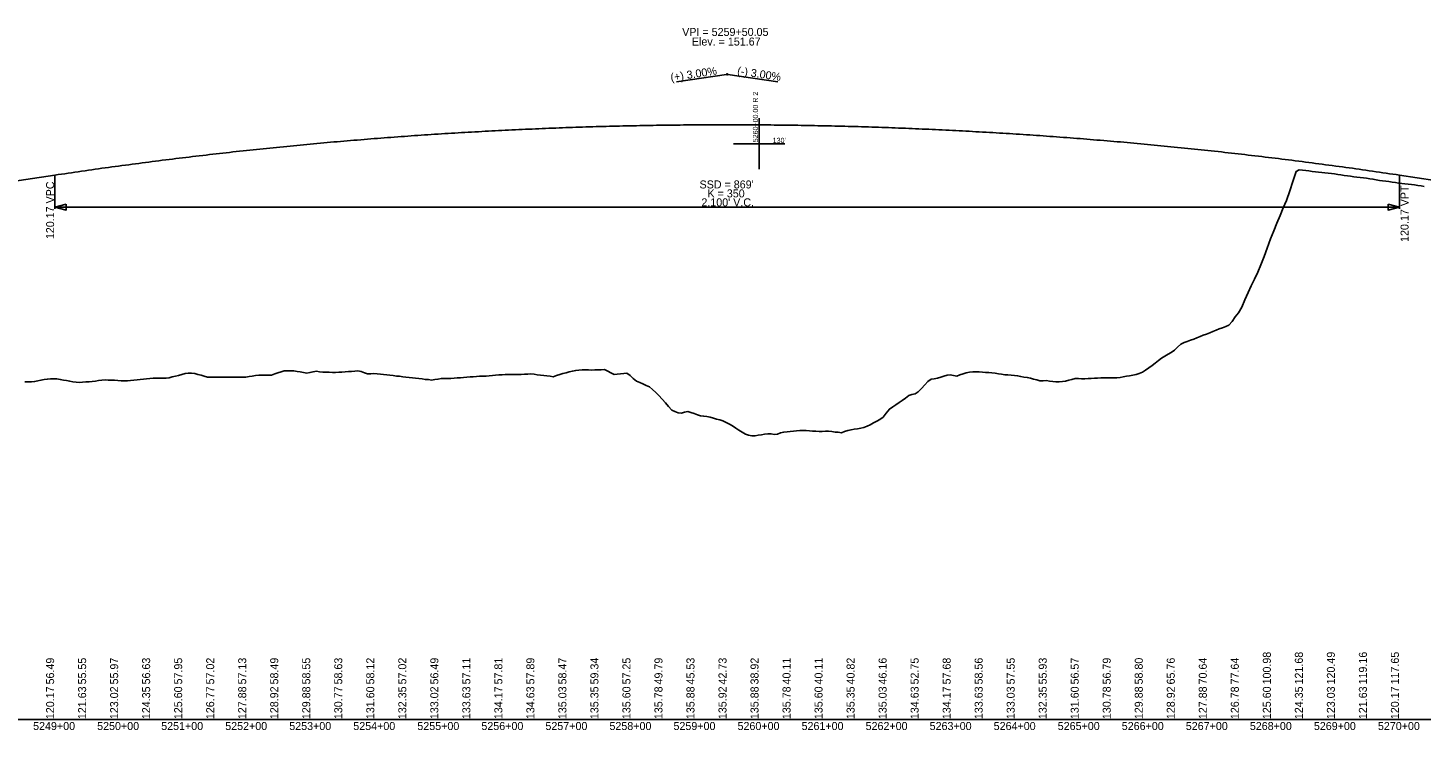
# Model space of a CAD drawing. Extents: x 2147288 to 2220488, y 740833 to 759333.
# Drawn here: x 2157239 to 2159415, y 758067 to 759164 of the extents above; entities that cross this region are included whole.
import ezdxf

# ---------------------------------------------------------------- set-up
doc = ezdxf.new("R2010")
doc.units = 0
for name, color, linetype in [('RD_DDB_GradeTX', 7, 'Continuous'), ('RD_DDB_Profile_EX', 7, 'Continuous'), ('RD_DDB_Profile_Lbl', 7, 'Continuous'), ('RD_DDB_Profile_PR', 7, 'Continuous'), ('RD_DDB_StaTX', 7, 'Continuous'), ('RD_DDB_StripGrade', 7, 'Continuous'), ('RD_DDB_VCLbl', 7, 'Continuous'), ('RD_GPK_Profile_Cell', 7, 'Continuous')]:
    doc.layers.add(name, color=color, linetype=linetype)

msp = doc.modelspace()

# ---------------------------------------------------------------- linework, layer by layer
at = {"layer": 'RD_DDB_GradeTX'}
for p, q in [((2158252, 759079.9), (2158330.1, 759091.6)), ((2158410.2, 759079.9), (2158332.1, 759091.6))]:
    msp.add_line(p, q, dxfattribs=at)
msp.add_circle((2158331.1, 759091.8), 1, dxfattribs=at)
at = {"layer": 'RD_DDB_Profile_EX'}
for points in [[(2159034.6, 758665.4), (2159039.6, 758669.9), (2159044.6, 758672.7), (2159049.6, 758674.2), (2159054.6, 758676.2), (2159059.6, 758678.2), (2159064.6, 758680.1), (2159069.6, 758682.1), (2159074.6, 758684.1), (2159079.6, 758686), (2159084.6, 758688), (2159089.6, 758690), (2159094.6, 758691.9), (2159099.6, 758693.9), (2159104.6, 758695.9), (2159109.6, 758697.8), (2159114.6, 758699.7), (2159119.6, 758705.5), (2159124.6, 758713), (2159129.6, 758718.9), (2159134.6, 758727.9), (2159139.6, 758739.3), (2159144.6, 758750.7), (2159149.6, 758761.4), (2159154.6, 758771.7), (2159159.6, 758782.7), (2159164.6, 758794.2), (2159169.6, 758806.9), (2159174.6, 758820.3), (2159179.6, 758834.5), (2159184.6, 758847.4), (2159189.6, 758859.5), (2159194.6, 758871.3), (2159199.6, 758883), (2159204.6, 758894.8), (2159209.6, 758909.7), (2159214.6, 758924.2), (2159219.6, 758940.1), (2159224.6, 758942.5), (2159229.6, 758942), (2159234.6, 758941.4), (2159239.6, 758940.9), (2159244.6, 758940.2), (2159249.6, 758939.6), (2159254.6, 758939.1), (2159259.6, 758938.5), (2159264.6, 758937.9), (2159269.6, 758937.3), (2159274.6, 758936.8), (2159279.6, 758936.1), (2159284.6, 758935.4), (2159289.6, 758934.7), (2159294.6, 758933.9), (2159299.6, 758933.3), (2159304.6, 758932.6), (2159309.6, 758931.9), (2159314.6, 758931.3), (2159319.6, 758930.7), (2159324.6, 758930.2), (2159329.6, 758929.5), (2159334.6, 758928.7), (2159339.6, 758928), (2159344.6, 758926.9), (2159349.6, 758926.1), (2159354.6, 758925.6), (2159359.6, 758924.9), (2159364.6, 758924.2), (2159369.6, 758923.4), (2159374.6, 758922.6), (2159379.6, 758921.9), (2159384.6, 758921.2), (2159389.6, 758920.6), (2159394.6, 758920.1), (2159399.6, 758919.5), (2159404.6, 758918.9), (2159409.6, 758918.2), (2159414.6, 758917.4), (2159419.6, 758916.6)], [(2158534.6, 758538.1), (2158539.6, 758538.9), (2158544.6, 758540.2), (2158549.6, 758542.2), (2158554.6, 758544.3), (2158559.6, 758547.1), (2158564.6, 758549.9), (2158569.6, 758552.7), (2158574.6, 758555.9), (2158579.6, 758562.3), (2158584.6, 758568.7), (2158589.6, 758572.3), (2158594.6, 758575.6), (2158599.6, 758578.9), (2158604.6, 758582.2), (2158609.6, 758586), (2158614.6, 758589.8), (2158619.6, 758591.7), (2158624.6, 758592.3), (2158629.6, 758595.5), (2158634.6, 758601), (2158639.6, 758606.4), (2158644.6, 758611.9), (2158649.6, 758615.4), (2158654.6, 758616.1), (2158659.6, 758617), (2158664.6, 758618.5), (2158669.6, 758620), (2158674.6, 758621.5), (2158679.6, 758622.2), (2158684.6, 758621), (2158689.6, 758620.4), (2158694.6, 758622.1), (2158699.6, 758623.8), (2158704.6, 758625.5), (2158709.6, 758626.6), (2158714.6, 758627), (2158719.6, 758627.1), (2158724.6, 758626.7), (2158729.6, 758626.3), (2158734.6, 758626), (2158739.6, 758625.7), (2158744.6, 758625.5), (2158749.6, 758624.8), (2158754.6, 758624), (2158759.6, 758623.2), (2158764.6, 758622.4), (2158769.6, 758622.1), (2158774.6, 758621.7), (2158779.6, 758621.4), (2158784.6, 758620.7), (2158789.6, 758619.5), (2158794.6, 758618.7), (2158799.6, 758618.1), (2158804.6, 758617), (2158809.6, 758615.6), (2158814.6, 758614.2), (2158819.6, 758612.8), (2158824.6, 758613), (2158829.6, 758613.3), (2158834.6, 758612.6), (2158839.6, 758612), (2158844.6, 758611.3), (2158849.6, 758611.1), (2158854.6, 758611.6), (2158859.6, 758612.5), (2158864.6, 758613.8), (2158869.6, 758615.1), (2158874.6, 758616.3), (2158879.6, 758616.3), (2158884.6, 758616.1), (2158889.6, 758616.2), (2158894.6, 758616.4), (2158899.6, 758616.6), (2158904.6, 758616.8), (2158909.6, 758617.2), (2158914.6, 758617.5), (2158919.6, 758617.4), (2158924.6, 758617.4), (2158929.6, 758617.4), (2158934.6, 758617.4), (2158939.6, 758617.4), (2158944.6, 758618.1), (2158949.6, 758619), (2158954.6, 758619.9), (2158959.6, 758620.8), (2158964.6, 758621.7), (2158969.6, 758622.6), (2158974.6, 758624.2), (2158979.6, 758626.5), (2158984.6, 758629.6), (2158989.6, 758633.1), (2158994.6, 758636.6), (2158999.6, 758640.5), (2159004.6, 758644.5), (2159009.6, 758648.4), (2159014.6, 758651.5), (2159019.6, 758654.4), (2159024.6, 758657.2), (2159029.6, 758660.9), (2159034.6, 758665.4)], [(2157234.6, 758611.4), (2157239.6, 758611.4), (2157244.6, 758611.3), (2157249.6, 758611.8), (2157254.6, 758612.8), (2157259.6, 758613.7), (2157264.6, 758614.7), (2157269.6, 758615.7), (2157274.6, 758615.9), (2157279.6, 758615.9), (2157284.6, 758615.8), (2157289.6, 758615.1), (2157294.6, 758614.1), (2157299.6, 758613.2), (2157304.6, 758612.2), (2157309.6, 758611.5), (2157314.6, 758611), (2157319.6, 758610.4), (2157324.6, 758610.6), (2157329.6, 758611.1), (2157334.6, 758611.5), (2157339.6, 758612), (2157344.6, 758612.6), (2157349.6, 758613.3), (2157354.6, 758614), (2157359.6, 758614.2), (2157364.6, 758614), (2157369.6, 758613.9), (2157374.6, 758613.7), (2157379.6, 758613.4), (2157384.6, 758613.1), (2157389.6, 758612.8), (2157394.6, 758613.1), (2157399.6, 758613.4), (2157404.6, 758613.7), (2157409.6, 758614.3), (2157414.6, 758614.9), (2157419.6, 758615.5), (2157424.6, 758616), (2157429.6, 758616.5), (2157434.6, 758616.9), (2157439.6, 758616.9), (2157444.6, 758616.9), (2157449.6, 758616.8), (2157454.6, 758616.8), (2157459.6, 758617.7), (2157464.6, 758618.9), (2157469.6, 758620.1), (2157474.6, 758621.4), (2157479.6, 758622.8), (2157484.6, 758624.1), (2157489.6, 758624.9), (2157494.6, 758624.6), (2157499.6, 758624.3), (2157504.6, 758622.9), (2157509.6, 758621.5), (2157514.6, 758620.2), (2157519.6, 758618.8), (2157524.6, 758618.6), (2157529.6, 758618.5), (2157534.6, 758618.5)], [(2157534.6, 758618.5), (2157539.6, 758618.6), (2157544.6, 758618.7), (2157549.6, 758618.7), (2157554.6, 758618.6), (2157559.6, 758618.5), (2157564.6, 758618.5), (2157569.6, 758618.4), (2157574.6, 758618.6), (2157579.6, 758618.8), (2157584.6, 758619.6), (2157589.6, 758620.4), (2157594.6, 758621), (2157599.6, 758621.5), (2157604.6, 758621.9), (2157609.6, 758621.9), (2157614.6, 758621.7), (2157619.6, 758621.8), (2157624.6, 758623.6), (2157629.6, 758625.3), (2157634.6, 758627.1), (2157639.6, 758628.6), (2157644.6, 758628.6), (2157649.6, 758628.5), (2157654.6, 758628.4), (2157659.6, 758627.6), (2157664.6, 758626.7), (2157669.6, 758625.8), (2157674.6, 758625), (2157679.6, 758625.8), (2157684.6, 758627), (2157689.6, 758627.8), (2157694.6, 758627.1), (2157699.6, 758626.4), (2157704.6, 758626.2), (2157709.6, 758626.2), (2157714.6, 758626.1), (2157719.6, 758626.1), (2157724.6, 758626.2), (2157729.6, 758626.5), (2157734.6, 758626.8), (2157739.6, 758627.2), (2157744.6, 758627.6), (2157749.6, 758628), (2157754.6, 758628.4), (2157759.6, 758627.3), (2157764.6, 758625.5), (2157769.6, 758623.9), (2157774.6, 758624), (2157779.6, 758624.1), (2157784.6, 758623.8), (2157789.6, 758623.3), (2157794.6, 758622.7), (2157799.6, 758622.2), (2157804.6, 758621.6), (2157809.6, 758621), (2157814.6, 758620.4), (2157819.6, 758619.9), (2157824.6, 758619.3), (2157829.6, 758618.7), (2157834.6, 758618.1), (2157839.6, 758617.5), (2157844.6, 758617), (2157849.6, 758616.4), (2157854.6, 758615.8), (2157859.6, 758615.2), (2157864.6, 758614.7), (2157869.6, 758614.1), (2157874.6, 758614.7), (2157879.6, 758615.6), (2157884.6, 758616.4), (2157889.6, 758616.4), (2157894.6, 758616.4), (2157899.6, 758616.6), (2157904.6, 758617), (2157909.6, 758617.3), (2157914.6, 758617.7), (2157919.6, 758618.1), (2157924.6, 758618.5), (2157929.6, 758618.9), (2157934.6, 758619.3), (2157939.6, 758619.7), (2157944.6, 758620), (2157949.6, 758620.1), (2157954.6, 758620.2), (2157959.6, 758620.6), (2157964.6, 758621.2), (2157969.6, 758621.8), (2157974.6, 758622.1), (2157979.6, 758622.4), (2157984.6, 758622.7), (2157989.6, 758623), (2157994.6, 758622.9), (2157999.6, 758622.7), (2158004.6, 758622.6), (2158009.6, 758622.9), (2158014.6, 758623.1), (2158019.6, 758623.4), (2158024.6, 758623.6), (2158029.6, 758623.1), (2158034.6, 758622.4)], [(2158034.6, 758622.4), (2158039.6, 758621.7), (2158044.6, 758621.1), (2158049.6, 758620.5), (2158054.6, 758619.9), (2158059.6, 758619.3), (2158064.6, 758621), (2158069.6, 758622.6), (2158074.6, 758624.1), (2158079.6, 758625.4), (2158084.6, 758626.7), (2158089.6, 758628), (2158094.6, 758629.2), (2158099.6, 758629.7), (2158104.6, 758630.2), (2158109.6, 758630.2), (2158114.6, 758629.9), (2158119.6, 758629.7), (2158124.6, 758629.9), (2158129.6, 758630.1), (2158134.6, 758630.3), (2158139.6, 758630.4), (2158144.6, 758628.2), (2158149.6, 758625.2), (2158154.6, 758623), (2158159.6, 758623.4), (2158164.6, 758623.9), (2158169.6, 758624.4), (2158174.6, 758624.9), (2158179.6, 758621.1), (2158184.6, 758616.5), (2158189.6, 758612.6), (2158194.6, 758610.3), (2158199.6, 758608), (2158204.6, 758605.8), (2158209.6, 758603.5), (2158214.6, 758599.1), (2158219.6, 758594.6), (2158224.6, 758589.7), (2158229.6, 758584.1), (2158234.6, 758578.4), (2158239.6, 758572.8), (2158244.6, 758567.2), (2158249.6, 758564.9), (2158254.6, 758562.7), (2158259.6, 758562.5), (2158264.6, 758563.9), (2158269.6, 758564.9), (2158274.6, 758563.2), (2158279.6, 758561.6), (2158284.6, 758559.9), (2158289.6, 758558.3), (2158294.6, 758557.4), (2158299.6, 758556.9), (2158304.6, 758556.1), (2158309.6, 758554.7), (2158314.6, 758553.2), (2158319.6, 758551.7), (2158324.6, 758550.2), (2158329.6, 758547.9), (2158334.6, 758545.2), (2158339.6, 758542.3), (2158344.6, 758539.1), (2158349.6, 758535.9), (2158354.6, 758532.8), (2158359.6, 758529.6), (2158364.6, 758528.2), (2158369.6, 758527.1), (2158374.6, 758527), (2158379.6, 758527.8), (2158384.6, 758528.6), (2158389.6, 758529.4), (2158394.6, 758530.2), (2158399.6, 758529.8), (2158404.6, 758529), (2158409.6, 758529.7), (2158414.6, 758531.5), (2158419.6, 758532.8), (2158424.6, 758533.3), (2158429.6, 758533.8), (2158434.6, 758534.4), (2158439.6, 758534.9), (2158444.6, 758535.1), (2158449.6, 758535.1), (2158454.6, 758535), (2158459.6, 758534.6), (2158464.6, 758534.3), (2158469.6, 758534), (2158474.6, 758533.7), (2158479.6, 758533.9), (2158484.6, 758534.2), (2158489.6, 758534.1), (2158494.6, 758533.5), (2158499.6, 758532.9), (2158504.6, 758532.4), (2158509.6, 758531.8), (2158514.6, 758533.5), (2158519.6, 758535.4), (2158524.6, 758536.5), (2158529.6, 758537.3), (2158534.6, 758538.1)]]:
    msp.add_lwpolyline(points, dxfattribs=at)
at = {"layer": 'RD_DDB_Profile_PR'}
for p, q in [((2156931.1, 758881.8), (2157281.1, 758934.3)), ((2159381.1, 758934.3), (2159706.2, 758885.5))]:
    msp.add_line(p, q, dxfattribs=at)
msp.add_spline([(2157281.1, 758934.3), (2157323.1, 758940.4), (2157365.1, 758946.4), (2157407.1, 758952), (2157449.1, 758957.5), (2157491.1, 758962.6), (2157533.1, 758967.5), (2157575.1, 758972.2), (2157617.1, 758976.6), (2157659.1, 758980.8), (2157701.1, 758984.7), (2157743.1, 758988.3), (2157785.1, 758991.7), (2157827.1, 758994.9), (2157869.1, 758997.8), (2157911.1, 759000.4), (2157953.1, 759002.8), (2157995.1, 759005), (2158037.1, 759006.8), (2158079.1, 759008.5), (2158121.1, 759009.9), (2158163.1, 759011), (2158205.1, 759011.9), (2158247.1, 759012.5), (2158289.1, 759012.9), (2158331.1, 759013), (2158373.1, 759012.9), (2158415.1, 759012.5), (2158457.1, 759011.9), (2158499.1, 759011), (2158541.1, 759009.9), (2158583.1, 759008.5), (2158625.1, 759006.8), (2158667.1, 759005), (2158709.1, 759002.8), (2158751.1, 759000.4), (2158793.1, 758997.8), (2158835.1, 758994.9), (2158877.1, 758991.7), (2158919.1, 758988.3), (2158961.1, 758984.7), (2159003.1, 758980.8), (2159045.1, 758976.6), (2159087.1, 758972.2), (2159129.1, 758967.5), (2159171.1, 758962.6), (2159213.1, 758957.5), (2159255.1, 758952), (2159297.1, 758946.4), (2159339.1, 758940.4), (2159381.1, 758934.3)], degree=3, dxfattribs=at)
at = {"layer": 'RD_DDB_VCLbl'}
for p, q in [((2157281.1, 758881.8), (2157281.1, 758934.3)), ((2159381.1, 758881.8), (2159381.1, 758934.3)), ((2157281.1, 758884.3), (2159381.1, 758884.3))]:
    msp.add_line(p, q, dxfattribs=at)
for points in [[(2157299.1, 758888.8), (2157281.1, 758884.3), (2157299.1, 758879.8)], [(2159363.1, 758888.8), (2159381.1, 758884.3), (2159363.1, 758879.8)]]:
    msp.add_lwpolyline(points, close=True, dxfattribs=at)
at = {"layer": 'RD_GPK_Profile_Cell'}
for p, q in [((2158381.1, 759023.4), (2158381.1, 758943.4)), ((2158421.1, 758983.4), (2158341.1, 758983.4)), ((2148888.3, 758083.4), (2165888.3, 758083.4))]:
    msp.add_line(p, q, dxfattribs=at)

# ---------------------------------------------------------------- texts
at = {"layer": 'RD_DDB_GradeTX'}
for s, rotation, p in [('(+) 3.00%', 8.5308, (2158243.6, 759080.7)), ('(-) 3.00%', 351.4692, (2158346.2, 759091.5))]:
    msp.add_text(s, height=12.5, rotation=rotation, dxfattribs=at).set_placement(p)
at = {"layer": 'RD_DDB_Profile_Lbl'}
for s, p in [('VPI = 5259+50.05', (2158260.9, 759151.8)), ('Elev. = 151.67', (2158276, 759136.8))]:
    msp.add_text(s, height=12.5, dxfattribs=at).set_placement(p)
at = {"layer": 'RD_DDB_StaTX'}
for s, p in [('5249+00', (2157247.3, 758067.2)), ('5250+00', (2157347.3, 758067.2)), ('5251+00', (2157447.3, 758067.2)), ('5252+00', (2157547.3, 758067.2)), ('5253+00', (2157647.3, 758067.2)), ('5254+00', (2157747.3, 758067.2)), ('5255+00', (2157847.3, 758067.2)), ('5256+00', (2157947.3, 758067.2)), ('5257+00', (2158047.3, 758067.2)), ('5258+00', (2158147.3, 758067.2)), ('5259+00', (2158247.3, 758067.2)), ('5260+00', (2158347.3, 758067.2)), ('5261+00', (2158447.3, 758067.2)), ('5262+00', (2158547.3, 758067.2)), ('5263+00', (2158647.3, 758067.2)), ('5264+00', (2158747.3, 758067.2)), ('5265+00', (2158847.3, 758067.2)), ('5266+00', (2158947.3, 758067.2)), ('5267+00', (2159047.3, 758067.2)), ('5268+00', (2159147.3, 758067.2)), ('5269+00', (2159247.3, 758067.2)), ('5270+00', (2159347.3, 758067.2))]:
    msp.add_text(s, height=12.5, dxfattribs=at).set_placement(p)
at = {"layer": 'RD_DDB_StripGrade'}
for s, p in [('120.17 VPC', (2157280.1, 758834.3)), ('120.17 VPT', (2159395.2, 758829.9)), ('100.98', (2159180.1, 758138.4)), ('121.68', (2159230.1, 758138.4)), ('120.49', (2159280.1, 758138.4)), ('119.16', (2159330.1, 758138.4)), ('117.65', (2159380.1, 758138.4)), ('56.49', (2157280.1, 758138.4)), ('55.55', (2157330.1, 758138.4)), ('55.97', (2157380.1, 758138.4)), ('56.63', (2157430.1, 758138.4)), ('57.95', (2157480.1, 758138.4)), ('57.02', (2157530.1, 758138.4)), ('57.13', (2157580.1, 758138.4)), ('58.49', (2157630.1, 758138.4)), ('58.55', (2157680.1, 758138.4)), ('58.63', (2157730.1, 758138.4)), ('58.12', (2157780.1, 758138.4)), ('57.02', (2157830.1, 758138.4)), ('56.49', (2157880.1, 758138.4)), ('57.11', (2157930.1, 758138.4)), ('57.81', (2157980.1, 758138.4)), ('57.89', (2158030.1, 758138.4)), ('58.47', (2158080.1, 758138.4)), ('59.34', (2158130.1, 758138.4)), ('57.25', (2158180.1, 758138.4)), ('49.79', (2158230.1, 758138.4)), ('45.53', (2158280.1, 758138.4)), ('42.73', (2158330.1, 758138.4)), ('38.92', (2158380.1, 758138.4)), ('40.11', (2158430.1, 758138.4)), ('40.11', (2158480.1, 758138.4)), ('40.82', (2158530.1, 758138.4)), ('46.16', (2158580.1, 758138.4)), ('52.75', (2158630.1, 758138.4)), ('57.68', (2158680.1, 758138.4)), ('58.56', (2158730.1, 758138.4)), ('57.55', (2158780.1, 758138.4)), ('55.93', (2158830.1, 758138.4)), ('56.57', (2158880.1, 758138.4)), ('56.79', (2158930.1, 758138.4)), ('58.80', (2158980.1, 758138.4)), ('65.76', (2159030.1, 758138.4)), ('70.64', (2159080.1, 758138.4)), ('77.64', (2159130.1, 758138.4)), ('120.17', (2157280.1, 758084.2)), ('121.63', (2157330.1, 758084.2)), ('123.02', (2157380.1, 758084.2)), ('124.35', (2157430.1, 758084.2)), ('125.60', (2157480.1, 758084.2)), ('126.77', (2157530.1, 758084.2)), ('127.88', (2157580.1, 758084.2)), ('128.92', (2157630.1, 758084.2)), ('129.88', (2157680.1, 758084.2)), ('130.77', (2157730.1, 758084.2)), ('131.60', (2157780.1, 758084.2)), ('132.35', (2157830.1, 758084.2)), ('133.02', (2157880.1, 758084.2)), ('133.63', (2157930.1, 758084.2)), ('134.17', (2157980.1, 758084.2)), ('134.63', (2158030.1, 758084.2)), ('135.03', (2158080.1, 758084.2)), ('135.35', (2158130.1, 758084.2)), ('135.60', (2158180.1, 758084.2)), ('135.78', (2158230.1, 758084.2)), ('135.88', (2158280.1, 758084.2)), ('135.92', (2158330.1, 758084.2)), ('135.88', (2158380.1, 758084.2)), ('135.78', (2158430.1, 758084.2)), ('135.60', (2158480.1, 758084.2)), ('135.35', (2158530.1, 758084.2)), ('135.03', (2158580.1, 758084.2)), ('134.63', (2158630.1, 758084.2)), ('134.17', (2158680.1, 758084.2)), ('133.63', (2158730.1, 758084.2)), ('133.03', (2158780.1, 758084.2)), ('132.35', (2158830.1, 758084.2)), ('131.60', (2158880.1, 758084.2)), ('130.78', (2158930.1, 758084.2)), ('129.88', (2158980.1, 758084.2)), ('128.92', (2159030.1, 758084.2)), ('127.88', (2159080.1, 758084.2)), ('126.78', (2159130.1, 758084.2)), ('125.60', (2159180.1, 758084.2)), ('124.35', (2159230.1, 758084.2)), ('123.03', (2159280.1, 758084.2)), ('121.63', (2159330.1, 758084.2)), ('120.17', (2159380.1, 758084.2))]:
    msp.add_text(s, height=12.5, rotation=90, dxfattribs=at).set_placement(p)
at = {"layer": 'RD_DDB_VCLbl'}
for s, p in [("SSD = 869'", (2158288, 758913.5)), ("2,100' V.C.", (2158290.9, 758885.5)), ('K = 350', (2158300.4, 758899.5))]:
    msp.add_text(s, height=12.5, dxfattribs=at).set_placement(p)
at = {"layer": 'RD_GPK_Profile_Cell'}
msp.add_text('5260+00.00 R 2', height=8, rotation=90, dxfattribs=at).set_placement((2158379.3, 758985.7))
msp.add_text("130'", height=8, dxfattribs=at).set_placement((2158402.2, 758984.6))

doc.saveas('drawing.dxf')
